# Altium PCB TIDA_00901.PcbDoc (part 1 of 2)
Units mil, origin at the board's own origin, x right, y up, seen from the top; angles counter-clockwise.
Board outline 2500 x 2500 mil, 4 copper layers (Top Layer, GND, PVDD, Bottom Layer), stack 59.2 mil thick; 113 components, 73 nets, 335 pads, 307 vias.
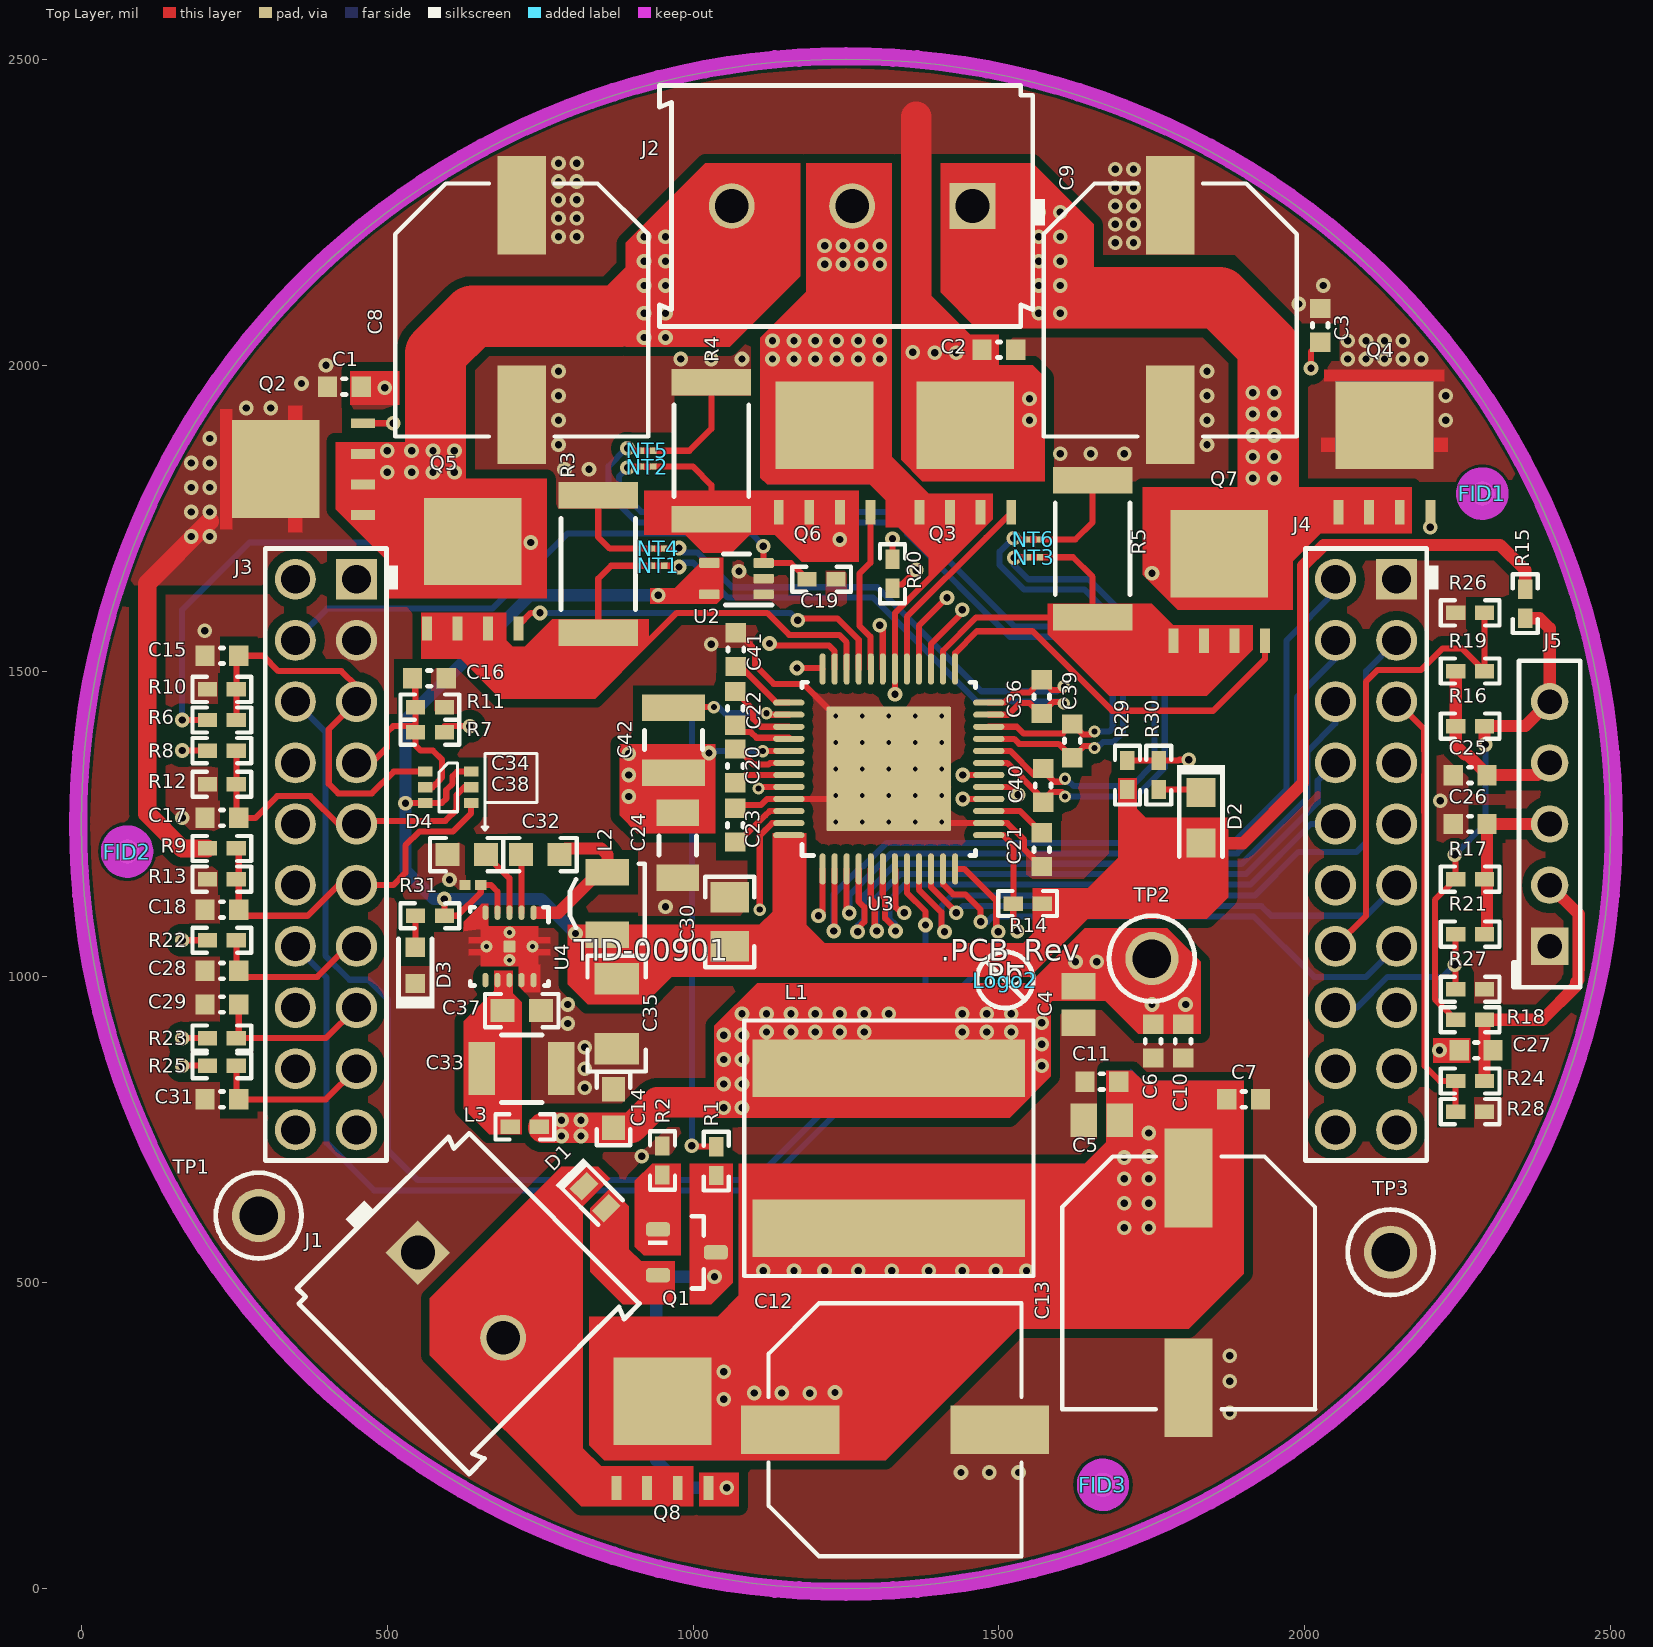
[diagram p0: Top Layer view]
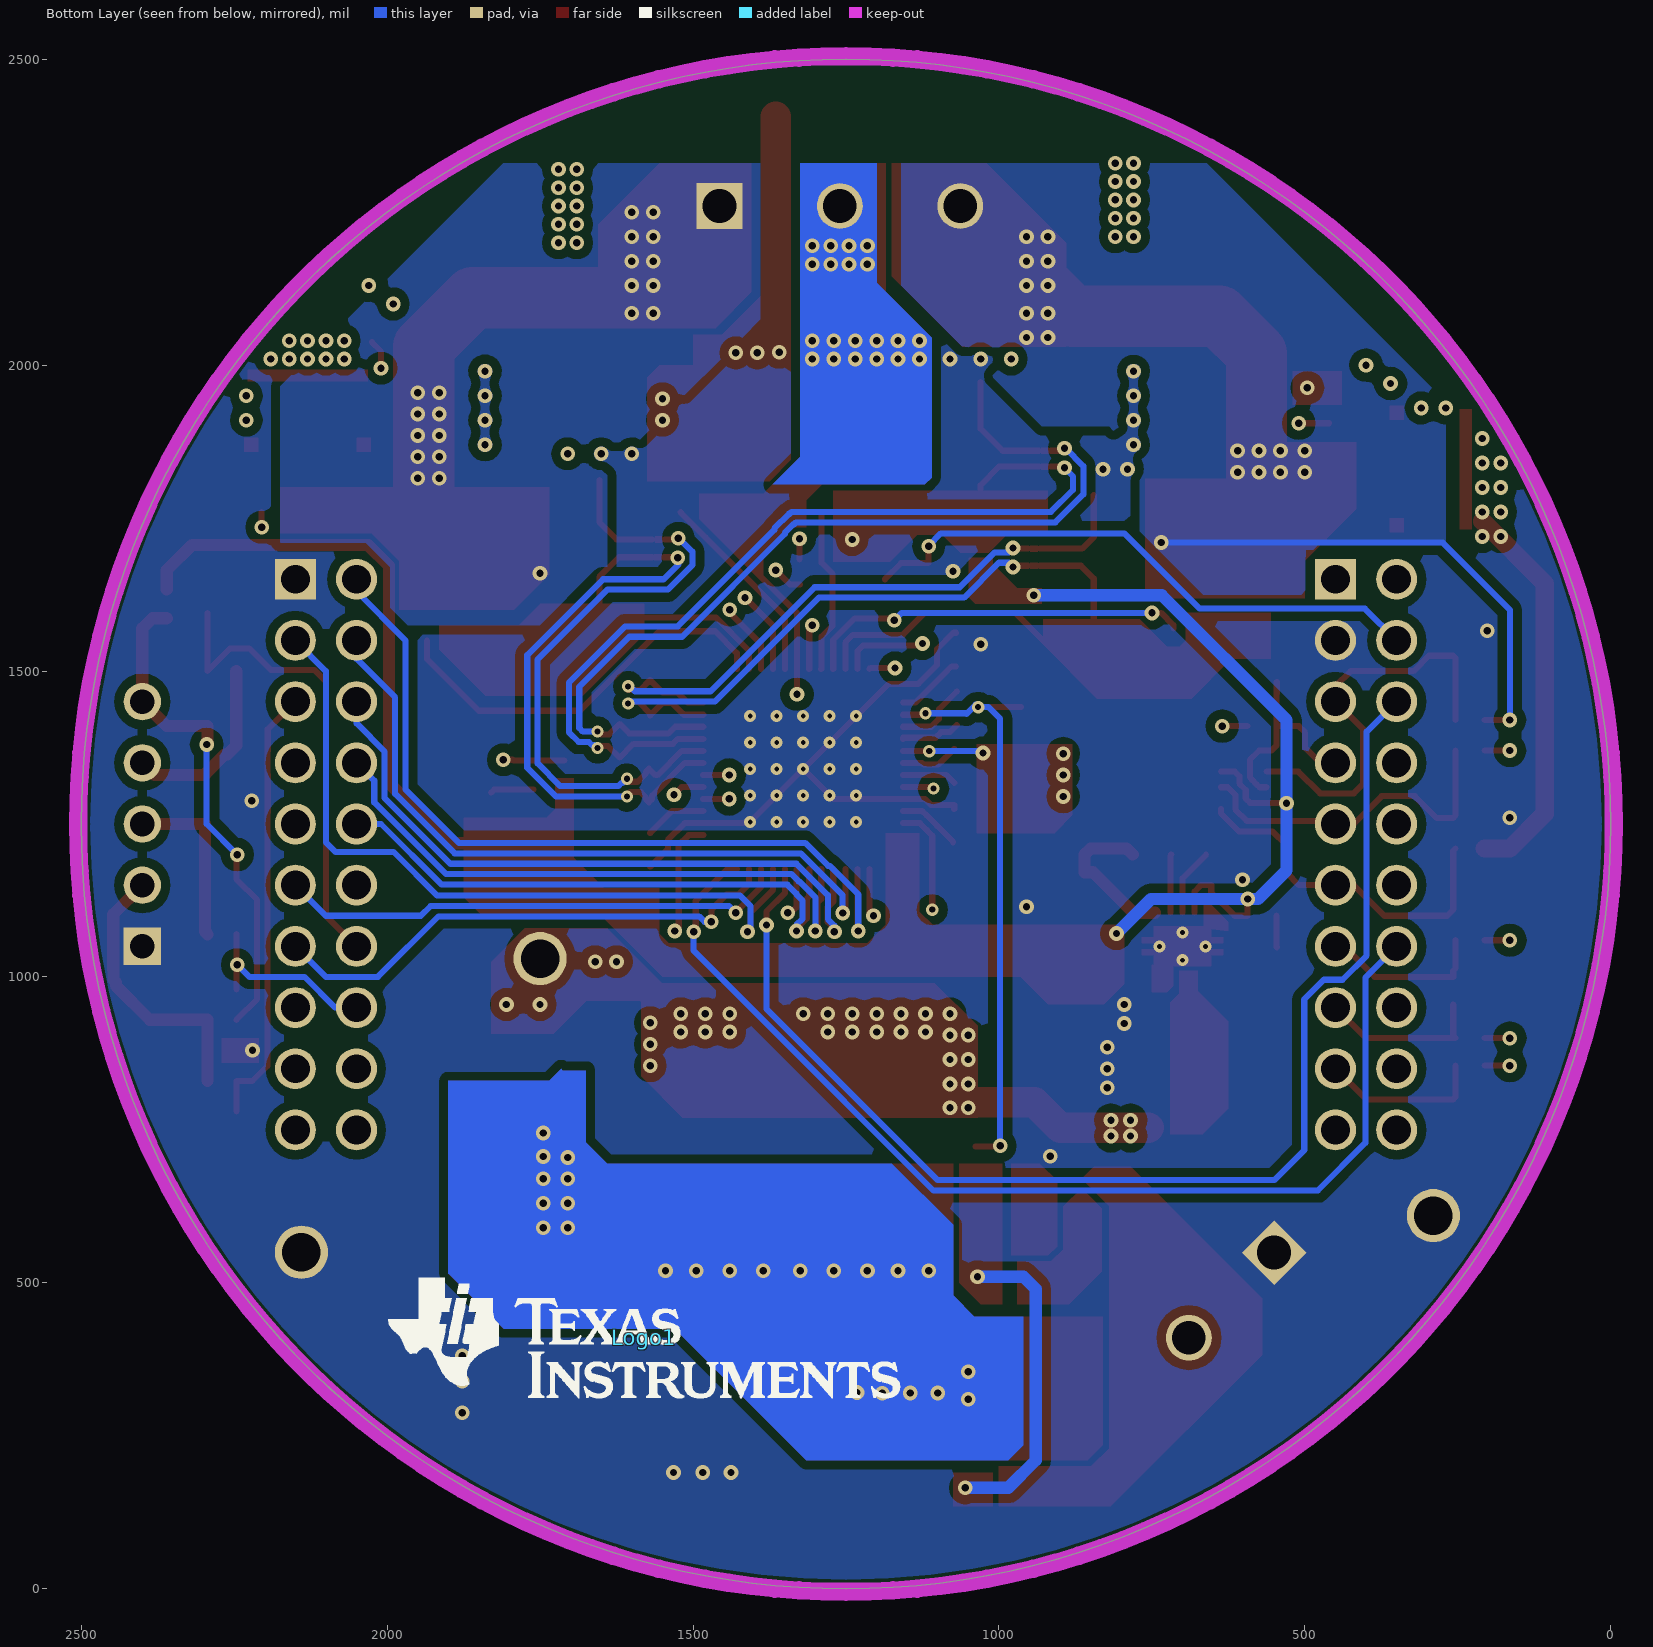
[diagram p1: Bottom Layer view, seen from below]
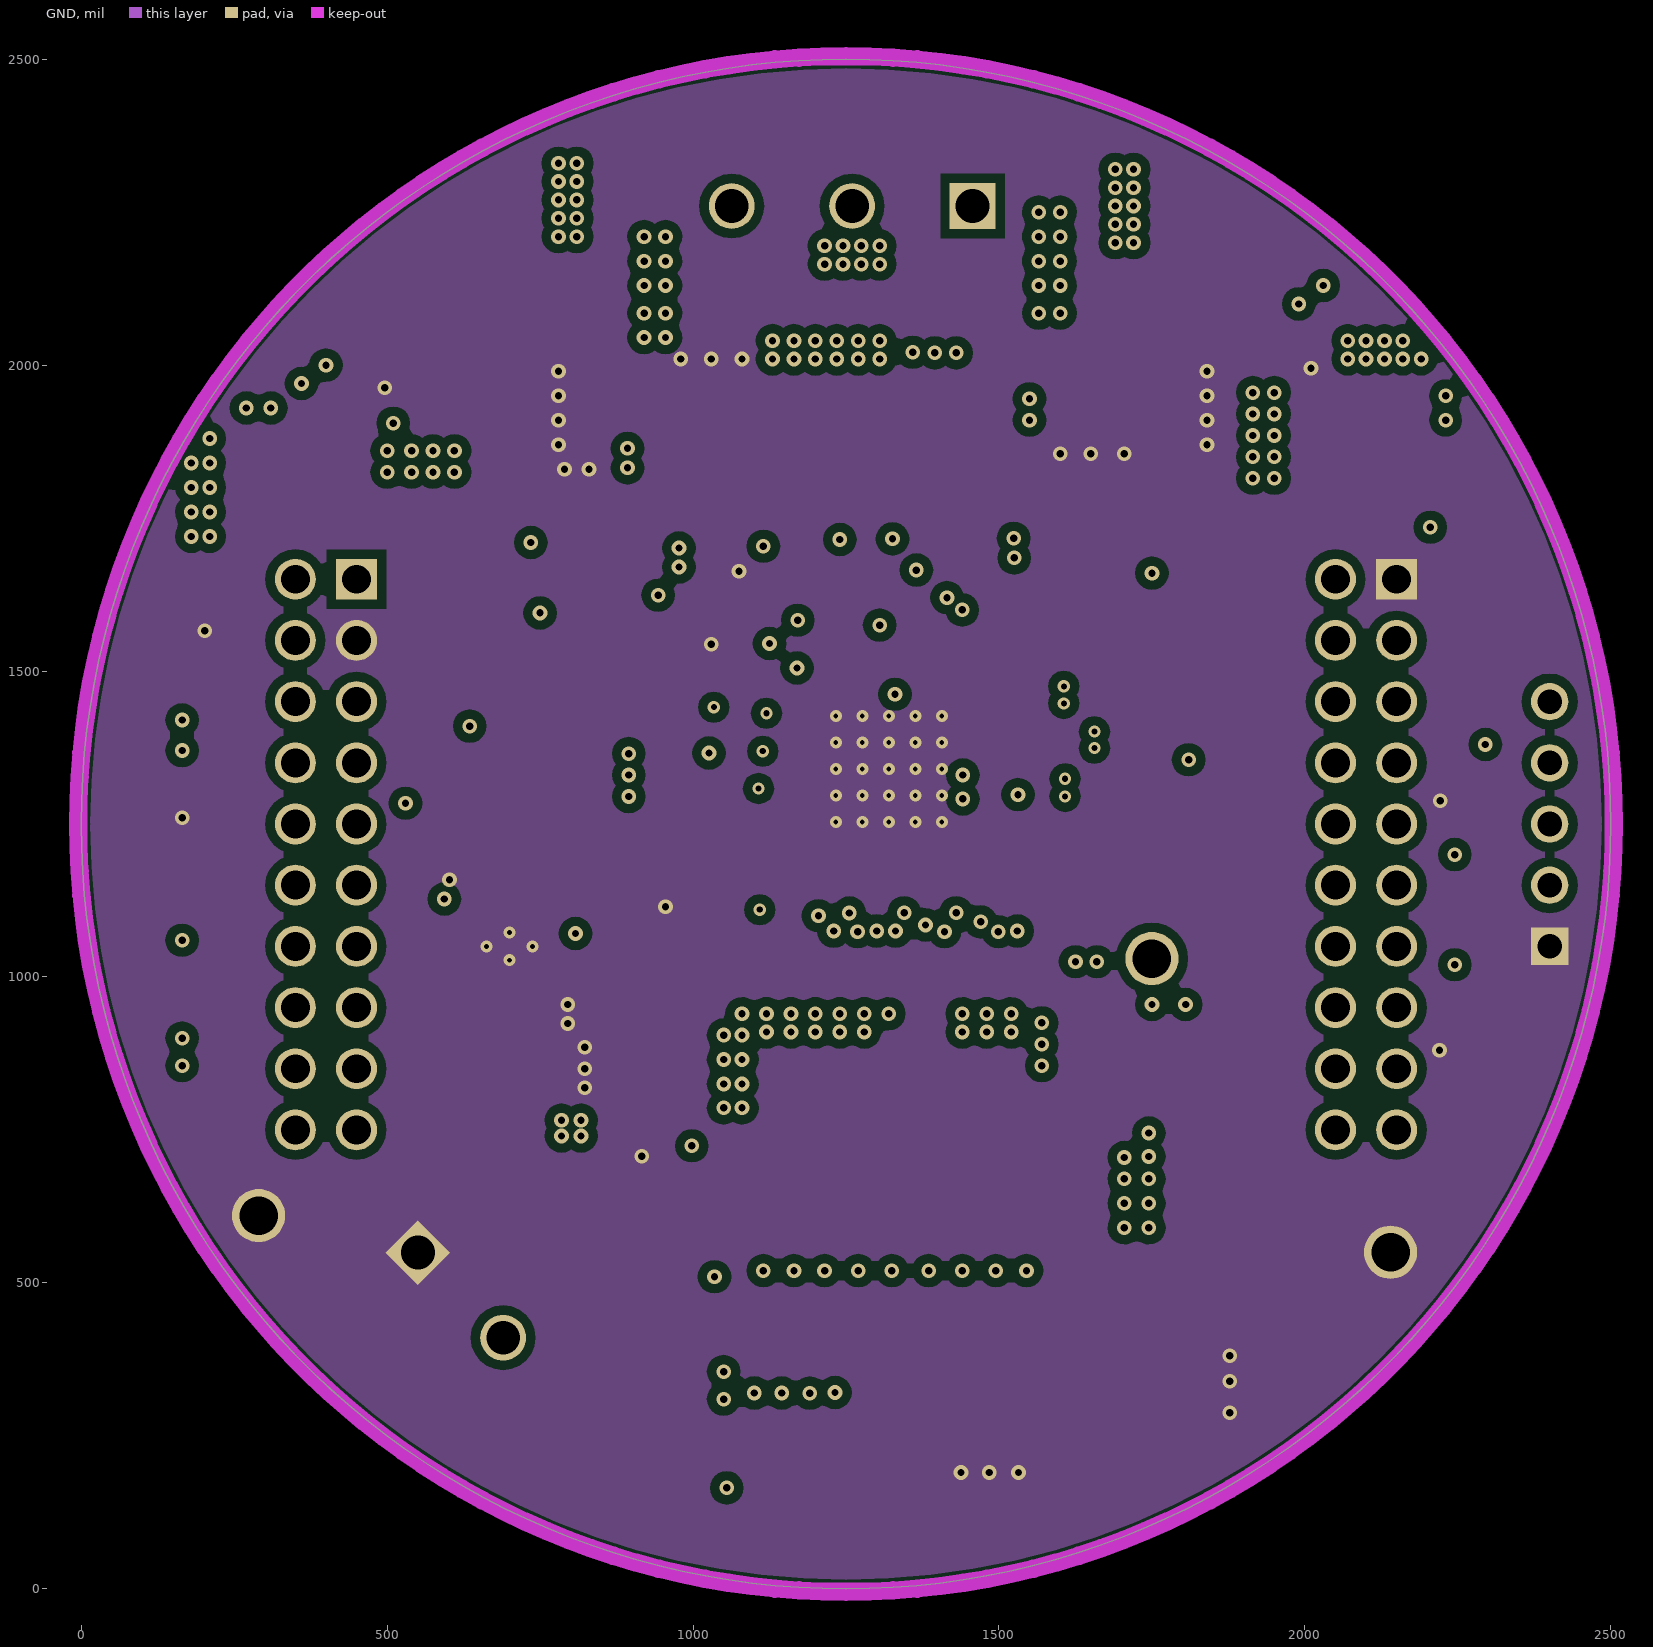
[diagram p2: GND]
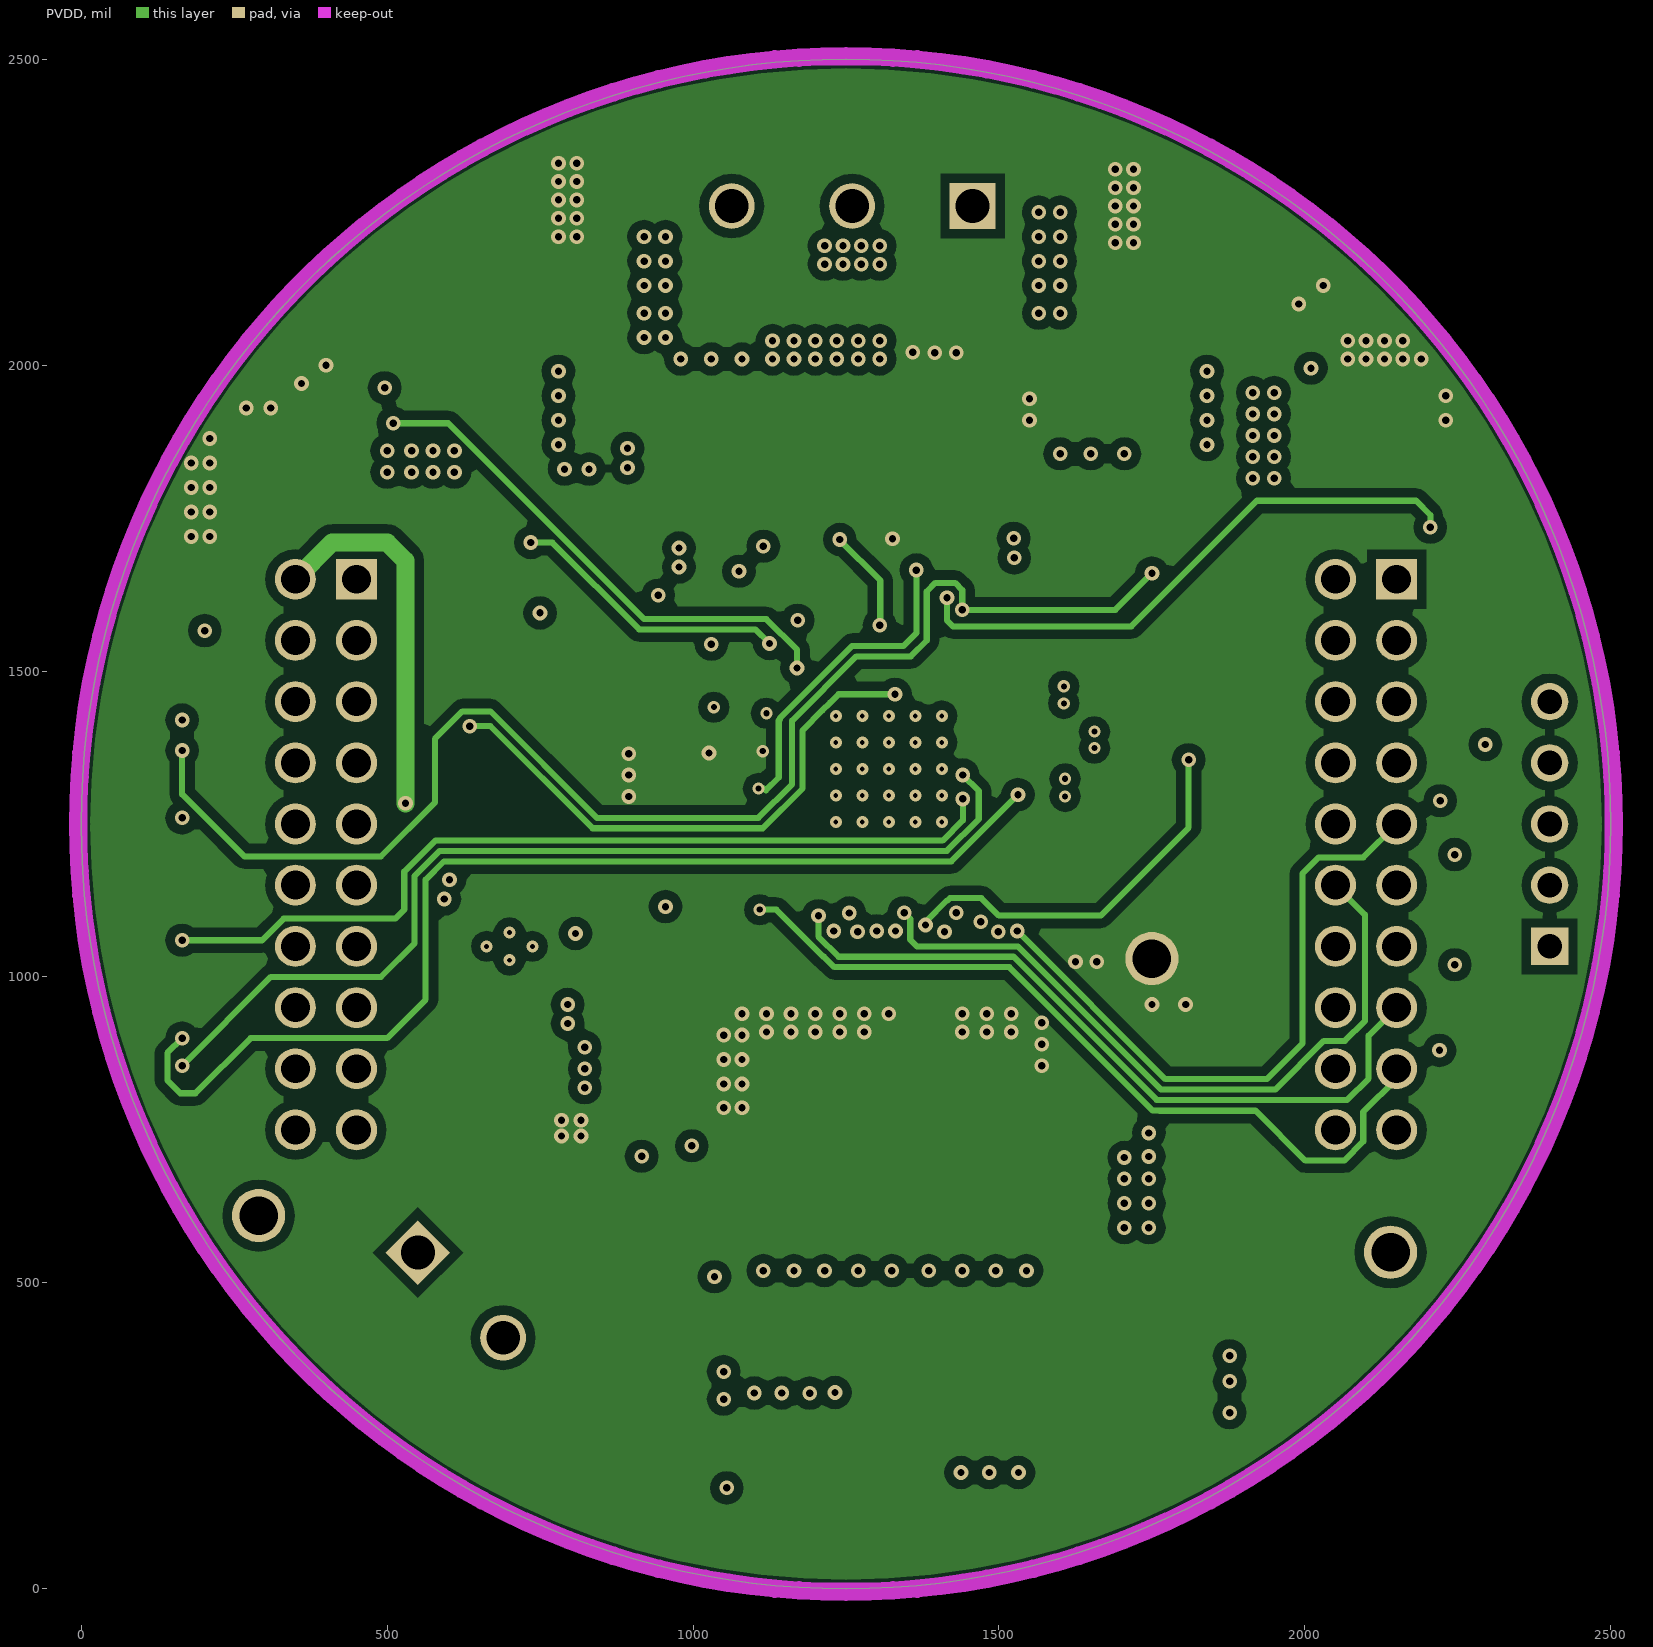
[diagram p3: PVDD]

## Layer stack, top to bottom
Top Solder: solder mask 0.4, Solder Resist, Dk 3.5
Top Layer: signal copper 2.8
Dielectric1: prepreg 10, FR-4, Dk 4.2
GND: signal copper 2.8
Dielectric 3: core 28, FR-4, Dk 4.2
PVDD: signal copper 2.8
Dielectric 2: prepreg 10, FR-4, Dk 4.2
Bottom Layer: signal copper 2.8
Bottom Solder: solder mask 0.4, Solder Resist, Dk 3.5

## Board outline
1250,0 cw(c1250,1250) 0,1250 cw(c1250,1250) 1250,2500 cw(c1250,1250) 2500,1250 cw(c1250,1250)

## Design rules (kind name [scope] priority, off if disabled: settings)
AcuteAngle [All] p1: minimum=4.50000000000000E+0001 checktracksonly=FALSE
AssemblyTestPointUsage [All] p1: valid=2
Clearance Clearance_Keepouts [((IsTrack Or IsArc) And Not InPoly) And IsFree and IsKeepOut vs ((IsTrack Or IsArc) And Not InPoly) And IsFree and IsKeepOut] p1: gap=0
Clearance Clearance_BoardEdge_MountingHoles [OnCopper and InComponentClass('Mounting Holes') vs IsKeepOut] p2: gap=20
Clearance Clearance_BoardEdge_Poly [OnCopper and InPoly vs IsKeepOut] p3: gap=5
Clearance Clearance_BoardEdge [OnCopper and Not InComponentClass('Logo') and not InComponentClass('FiducialMark') and not InRegion(1000,500,4000,800) and Not IsKeepout vs IsKeepOut] p4: gap=5
Clearance Clearance_Poly [InPolygon] p5: gap=15
Clearance [All] p6: gap=7
ComponentClearance ComponentClearance_MountingHoles_FiducialMarks [InComponentClass('Mounting Holes') vs InComponentClass('FiducialMark')] p1: gap=20 collisioncheckmode=3 verticalgap=10 showdistances=FALSE
ComponentClearance ComponentClearance_Shunt [InComponentClass('Header') vs InComponentClass('Shunt')] p2: gap=0 collisioncheckmode=3 verticalgap=0 showdistances=FALSE
ComponentClearance ComponentClearance_Logo [InComponentClass('Logo')] p3: gap=20 collisioncheckmode=3 verticalgap=10 showdistances=FALSE
ComponentClearance ComponentClearance_ScrewToNut [(HasFootprint('NY PMS 440 0025 PH')) vs (HasFootprint('Keystone_1902C'))] p4: gap=5 collisioncheckmode=3 verticalgap=10 showdistances=FALSE
ComponentClearance ComponentClearance_MountingHoles [InComponentClass('Mounting Holes')] p5: gap=20 collisioncheckmode=3 verticalgap=0 showdistances=FALSE
ComponentClearance ComponentClearance_SmallPassives [HasFootprint('0201*') or HasFootprint('0402*') or HasFootprint('0508') or HasFootprint('0603*') or HasFootprint('0612') or HasFootprint('0805*') or HasFootprint('0815*') or HasFootprint('0830*') or HasFootprint('1206*') or HasFootprint('1210*') or HasFootprint('1808*') or HasFootprint('1812*') or HasFootprint('1825*') or HasFootprint('2010*') or HasFootprint('2220*') or HasFootprint('2225*') or HasFootprint('2512*') or HasFootprint('2728*') or HasFootprint('3518*') vs HasFootprint('0201*') or HasFootprint('0402*') or HasFootprint('0508') or HasFootprint('0603*') or HasFootprint('0612') or HasFootprint('0805*') or HasFootprint('0815*') or HasFootprint('0830*') or HasFootprint('1206*') or HasFootprint('1210*') or HasFootprint('1808*') or HasFootprint('1812*') or HasFootprint('1825*') or HasFootprint('2010*') or HasFootprint('2220*') or HasFootprint('2225*') or HasFootprint('2512*') or HasFootprint('2728*') or HasFootprint('3518*')] p6: gap=10 collisioncheckmode=3 verticalgap=10 showdistances=FALSE
ComponentClearance ComponentClearance_THtoSMT [IsThruComponent vs IsSMTComponent] p7: gap=15 collisioncheckmode=3 verticalgap=20 showdistances=FALSE
ComponentClearance ComponentClearance_THtoTH [IsThruComponent vs IsThruComponent] p8: gap=15 collisioncheckmode=3 verticalgap=20 showdistances=FALSE
ComponentClearance [All] p9: gap=15 collisioncheckmode=3 verticalgap=10 showdistances=FALSE
DiffPairsRouting [All] p1: maxlimit=100 minlimit=7 mostfreqgap=7 toplayer_minwidth=10 toplayer_maxwidth=15 toplayer_prefwidth=10 midlayer1_minwidth=10 midlayer1_maxwidth=15 midlayer1_prefwidth=10 midlayer2_minwidth=10 midlayer2_maxwidth=15 midlayer2_prefwidth=10 bottomlayer_minwidth=10 bottomlayer_maxwidth=15 bottomlayer_prefwidth=10 maxuncoupledlength=1000
FabricationTestPointUsage TestPointUsage [All] p1: valid=2 allowmultiple=FALSE
FabricationTestpoint Testpoint [All] p1: side=3 testpointundercomponent=TRUE minsize=40 maxsize=100 preferedsize=60 minholesize=0 maxholesize=40 preferedholesize=32 testpointgrid=1 allowsidetop=TRUE allowsidebottom=TRUE usegrid=TRUE gridtolerance=0.01
FanoutControl Fanout_LCC [IsLCC] p1: bgadir=Out bgaviamode=Centered fanoutstyle=Auto fanoutdirection=Alternating viagrid=1 // Fanout_LCC (Default Rule)
FanoutControl Fanout_BGA [IsBGA] p2: bgadir=Out bgaviamode=Centered fanoutstyle=Auto fanoutdirection=Alternating viagrid=1 // Fanout_BGA (Default Rule)
FanoutControl Fanout_Default [All] p4: bgadir=Out bgaviamode=Centered fanoutstyle=Auto fanoutdirection=Alternating viagrid=1 // Fanout_Default (Default Rule)
FanoutControl Fanout_Small [(CompPinCount < 5)] p5: bgadir=Out bgaviamode=Centered fanoutstyle=Auto fanoutdirection=OutThenIn viagrid=1 // Fanout_Small (Default Rule)
HoleSize [All] p1: absolutevalues=TRUE maxlimit=251 minlimit=7 maxpercent=80.000 minpercent=20.000
Length All [All] p1: maxlimit=50000 minlimit=0
MinimumAnnularRing MinimumAnnularRing_ThermalPadVias [IsVia and InAnyComponent] p1: minimumring=3
MinimumAnnularRing [All] p2: minimumring=5
MinimumSolderMaskSliver MinimumSolderMaskSliver_Logo [InComponentClass('Logo') vs InComponentClass('Logo')] p1: minsoldermaskwidth=0.7
MinimumSolderMaskSliver [All] p2: minsoldermaskwidth=3.94
PlaneClearance [All] p1: clearance=10
PlaneConnect [All] p1: planeconnectstyle=Direct reliefexpansion=10 reliefentries=4 reliefconductorwidth=50 reliefairgap=10
PolygonConnect [All] p1: connectstyle=Direct reliefconductorwidth=10 reliefentries=4 polygonreliefangle="90 Angle" airgapwidth=10
RoutingVias ThermalPadVias [IsVia and InAnyComponent] p1: holewidth=7.87 width=19.68 viastyle="Through Hole" minholewidth=7.87 minwidth=19.68 maxholewidth=12.99 maxwidth=23.62
RoutingVias [All] p2: holewidth=16 width=34 viastyle="Through Hole" minholewidth=5 minwidth=15 maxholewidth=40 maxwidth=65
SilkToBoardRegionClearance [Not ((IsComment or IsDesignator) And (Hide <> 'False')) and not InRegion(1000,500,4000,800)] p1:
SilkToSilkClearance SilkToSilkClearance_Pb-FreeLogo [(HasFootprint('Pb-Free_Overlay_Medium') OR HasFootprint('Pb-Free_Overlay_Small')) vs (HasFootprint('Pb-Free_Overlay_Medium') OR HasFootprint('Pb-Free_Overlay_Small'))] p1: silktosilkclearance=0
SilkToSilkClearance [All] p2: silktosilkclearance=4
SilkToSolderMaskClearance SilkToComonentPadClearance [IsPad and InAnycomponent] p1: minsilkscreentomaskgap=5 clearancetoexposedcopper=TRUE
SilkToSolderMaskClearance "Silk to Solder Mask Opening" [All] p2: minsilkscreentomaskgap=4 clearancetoexposedcopper=FALSE
SolderMaskExpansion [All] p1: expansion=1.97
UnpouredPolygon [All] p1: allowunpoured=FALSE
Width [All] p1: maxlimit=100 minlimit=6 preferedwidth=10 checkconnectedcopper=TRUE
13 further rules are at their usual default settings.

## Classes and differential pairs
component class "TIDA 00901 Schematic 2": C1 C2 C3 C4 C5 C6 C7 C8 C9 C10 C11 C12 C13 C14 C15 C16 C17 C18 C19 C20 C21 C22 C23 C24 C25 C26 C27 C28 C29 C30 C31 C32 C33 C34 C35 C36 C37 C38 C39 C40 C41 C42 D1 D2 D3 D4 J1 J2 J3 J4 J5 L1 L2 L3 NT1 NT2 NT3 NT4 NT5 NT6 Q1 Q2 Q3 Q4 Q5 Q6 Q7 Q8 R1 R2 R3 R4 R5 R6 R7 R8 R9 R10 R11 R12 R13 R14 R15 R16 R17 R18 R19 R20 R21 R22 R23 R24 R25 R26 R27 R28 R29 R30 R31 TP1 TP2 TP3 U2 U3 U4
component class Logo: Logo1
component class TID_Hardware: FID1 FID2 FID3 Logo1 Logo2 ZZ1 ZZ2 ZZ3
component class FiducialMark: FID1 FID2 FID3
component class AssemblyNote: ZZ1 ZZ2 ZZ3
differential pair S1: +S1_P -S1_N
differential pair S2: +S2_P -S2_N
differential pair S3: +S3_P -S3_N

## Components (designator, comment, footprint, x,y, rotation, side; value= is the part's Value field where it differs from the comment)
C1 "UMK107AB7105KA-T" 0603L 430,1965 r0 top
C2 "UMK107AB7105KA-T" 0603L 1500,2025 r0 top
C3 "UMK107AB7105KA-T" 0603L 2025,2065 r270 top
C4 "GRM21BR71H105KA12L" 0805L 1630,955 r270 top
C5 "GRM21BR71H105KA12L" 0805L 1668,766 r180 top
C6 "C1608X7R1H104K" 0603L 1752,895 r270 top
C7 "C1608X7R1H104K" 0603L 1900,800 r0 top
C8 "EEE-FT1H331AP" SM_RADIAL_G 720,2090 r270 top
C9 "EEE-FT1H331AP" SM_RADIAL_G 1780,2090 r270 top
C10 "C1608X7R1H103K" 0603L 1801,895 r270 top
C11 "C1608X7R1H103K" 0603L 1668,829 r180 top
C12 "EEE-FT1H331AP" SM_RADIAL_G 1330,260 r0 top
C13 "EEE-FT1H331AP" SM_RADIAL_G 1810,500 r270 top
C14 "GRM188R71H104KA93D" 0603 870,785 r90 top
C15 "C0603C104J4RACTU" 0603L 230,1525 r180 top
C16 "C0603C104J4RACTU" 0603L 569,1488 r0 top
C17 "C0603C104J4RACTU" 0603L 230,1260 r180 top
C18 "C0603C104J4RACTU" 0603L 230,1110 r180 top
C19 "C0402C104K4RACAUTO" 0402 1210,1650 r0 top
C20 "C0603C473K1RACTU" 0603L 1069,1345 r90 top
C21 "C1608X7R1C105K" 0603L 1570,1208 r90 top
C22 "C0603C473K1RACTU" 0603L 1069,1439 r270 top
C23 "C1608X7R1C105K" 0603L 1069,1248 r270 top
C24 "GRM31CR71H475KA12L" 1206L 975,1215 r90 top
C25 "GRM188R71C102KA01D" 0603L 2270,1330 r180 top
C26 "GRM188R71C102KA01D" 0603L 2270,1250 r180 top
C27 "GRM188R71C102KA01D" 0603L 2280,880 r180 top
C28 "GRM188R71C222KA01D" 0603L 230,1010 r180 top
C29 "GRM188R71C222KA01D" 0603L 230,955 r180 top
C30 "C2012X7R1A106M125AC" 0805_HV 1060,1090 r90 top
C31 "GRM188R71C222KA01D" 0603L 230,800 r180 top
C32 "GRM188R71H104KA93D" 0603 750,1200 r0 top
C33 "C3225X7R1H106M250AC" 1210_280 720,850 r0 top
C34 "GRM188R71C105KA12D" 0603 630,1200 r180 top
C35 "GRM31CR71A226KE15L" 1206 875,940 r270 top
C36 "GRM188R71C102KA01D" 0603L 1570,1458 r90 top
C37 "GRM188R71H104KA93D" 0603 720,945 r0 top
C38 "GRM033R71A103KA01D" 0201 640,1150 r180 top
C39 "GRM188R71C102KA01D" 0603L 1620,1386 r90 top
C40 "GRM188R71C102KA01D" 0603L 1572,1313 r90 top
C41 "C1608X7R1C105K" 0603L 1070,1535 r90 top
C42 "GRM32ER72A225KA35L" 1210L 968,1387 r270 top
D1 "CD0603-S0180" Diode_0603 840,640 r315 top
D2 "LTST-C170KRKT" LED_LTST-C170 1830,1260 r90 top
D3 "LTST-C190KFKT" LED_LTST-C190 546,1019 r270 top
D4 "BAT54CDW-7-F" SOT-363 600,1310 r0 top
FID1 "Fiducial" Fiducial10-20 2290,1790 r0 top
FID2 "Fiducial" Fiducial10-20 75,1205 r0 top
FID3 "Fiducial" Fiducial10-20 1670,170 r0 top
J1 "282856-2" TE_282856-2 620,480 r315 top
J2 "282856-3" TE_282856-3 1260,2260 r180 top
J3 "CRD-081413-A-G" Major_CRD-081413-A-x 400,1200 r0 top locked
J4 "CRD-081413-A-G" Major_CRD-081413-A-x 2100,1200 r0 top locked
J5 "PPTC051LFBN-RC" Sullins_PPTC051LFBN-RC 2400,1250 r90 top
L1 "XAL1010-222MEB" XAL1010 1320,720 r90 top
L2 "SPM3012T-4R7M" SPM3012 860,1120 r270 top
L3 "BLM15AX601SN1D" 0402 725,755 r180 top
Logo1 "Texas Instruments" TI_Stacked_Overlay_Small 1580,410 r180 bottom
Logo2 "Pb-Free Symbol" Pb-Free_Overlay_Small 1510,995 r0 top
NT1 "Net-Tie" Net-Tie_10mil 943,1672 r180 top net-tie
NT2 "Net-Tie" Net-Tie_10mil 925,1834 r0 top net-tie
NT3 "Net-Tie" Net-Tie_10mil 1557,1686 r0 top net-tie
NT4 "Net-Tie" Net-Tie_10mil 943,1700 r180 top net-tie
NT5 "Net-Tie" Net-Tie_10mil 925,1860 r0 top net-tie
NT6 "Net-Tie" Net-Tie_10mil 1556,1715 r0 top net-tie
Q1 "BC846BLT1G" SOT-23 990,550 r0 top
Q2 "SQJ858AEP" PowerPAK_SO-8L 350,1830 r180 top
Q3 "SQJ858AEP" PowerPAK_SO-8L 1445,1870 r90 top
Q4 "SQJ858AEP" PowerPAK_SO-8L 2130,1870 r90 top
Q5 "SQJ858AEP" PowerPAK_SO-8L 640,1680 r90 top
Q6 "SQJ858AEP" PowerPAK_SO-8L 1215,1870 r90 top
Q7 "SQJ858AEP" PowerPAK_SO-8L 1860,1660 r90 top
Q8 "SQJ422EP-T1-GE3" PowerPAK_SO-8L 950,275 r90 top
R1 "CRCW040210K0JNED" 0402 1038,699 r270 top
R2 "CRCW040210K0JNED" 0402 950,700 r90 top
R3 "CRE2512-FZ-R007E-3" 2512L 845,1675 r270 top
R4 "CRE2512-FZ-R007E-3" 2512L 1030,1860 r270 top
R5 "CRE2512-FZ-R007E-3" 2512L 1653,1700 r270 top
R6 "CRCW040225K5FKED" 0402 230,1420 r180 top
R7 "CRCW040225K5FKED" 0402 570,1400 r0 top
R8 "CRCW040225K5FKED" 0402 230,1370 r180 top
R9 "CRCW040225K5FKED" 0402 230,1210 r180 top
R10 "CRCW04024K99FKED" 0402 230,1470 r0 top
R11 "CRCW04024K99FKED" 0402 570,1441 r180 top
R12 "CRCW04024K99FKED" 0402 230,1315 r0 top
R13 "CRCW04024K99FKED" 0402 230,1160 r0 top
R14 "CRCW040210K0JNED" 0402 1547,1120 r0 top
R15 "ERJ-2GE0R00X" 0402 2360,1610 r90 top
R16 "CRCW04021K00JNED" 0402 2270,1410 r0 top
R17 "CRCW04021K00JNED" 0402 2270,1160 r180 top
R18 "CRCW04021K00JNED" 0402 2270,930 r180 top
R19 "CRCW040210K0JNED" 0402 2270,1500 r0 top
R20 "CRCW0402100RFKED" 0402 1326,1659 r90 top
R21 "CRCW040210K0JNED" 0402 2270,1070 r180 top
R22 "CRCW040256R0JNED" 0402 230,1060 r180 top
R23 "CRCW040256R0JNED" 0402 230,900 r180 top
R24 "CRCW040210K0JNED" 0402 2270,830 r180 top
R25 "CRCW040256R0JNED" 0402 230,855 r180 top
R26 "CRCW040215K0JNED" 0402 2270,1595 r0 top
R27 "CRCW040215K0JNED" 0402 2270,980 r180 top
R28 "CRCW040215K0JNED" 0402 2270,780 r180 top
R29 "CRCW040210K0JNED" 0402 1710,1330 r270 top
R30 "CRCW0402330RJNED" 0402 1761,1330 r270 top
R31 "CRCW0402330RJNED" 0402 570,1100 r0 top
TP1 "5006" Keystone5006 290,610 r90 top
TP2 "5005" Keystone5005 1750,1030 r90 top
TP3 "5006" Keystone5006 2140,550 r90 top
U2 "LMT86QDCKRQ1" DCK0005A_N 1071,1651 r180 top
U3 "DRV8305NPHPQ1" PHP0048G_L 1320,1340 r90 top
U4 "LM53600NQDSXRQ1" DSX0010A 700,1050 r270 top
ZZ1 "These assemblies are ESD sensitive, ESD precautions shall be observed." AssemblyNote 125,3107.11 r0 top
ZZ2 "These assemblies must be clean and free from flux and all contaminants. Use of no clean flux is not acceptable." AssemblyNote 125,3018.56 r0 top
ZZ3 "These assemblies must comply with workmanship standards IPC-A-610 Class 2, unless otherwise specified." AssemblyNote 125,2930 r0 top

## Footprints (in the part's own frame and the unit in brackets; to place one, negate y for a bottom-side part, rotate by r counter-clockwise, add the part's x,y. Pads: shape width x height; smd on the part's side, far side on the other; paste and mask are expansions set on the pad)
0201 [mm] "Data from Kemet datasheet CC101_COM dated 7/28/11"
  rect 0.46x0.42 smd mask+0.048: 1(-0.33,0) 2(0.33,0)
  body extent -0.31,-0.16 0.31,0.16, height 0.26
0402 [mm] "0402 from SM-752 data"
  rect 0.8x0.6 smd: 1(-0.6,0) 2(0.6,0)
  silkscreen extent -1.22,-0.52 1.22,0.52, body extent -0.55,-0.3 0.55,0.3, height 0.6
0603 [mm] "0603 from SM-752 data"
  rect 1x0.95 smd: 1(-0.8,0) 2(0.8,0)
  silkscreen extent -1.52,-0.69 1.52,0.69, body extent -0.87,-0.47 0.87,0.47, height 1
0603L [mm] "0603 from SM-752 data"
  rect 0.8x0.85 smd: 1(-0.7,0) 2(0.7,0)
  silkscreen extent -0.07,-0.33 0.07,0.33, body extent -0.87,-0.47 0.87,0.47, height 1
0805_HV [mil] "0805 with 30mil clearance between pads"
  rect 50x63 smd: 1(-40,0) 2(40,0)
  silkscreen extent -74,-40 74,40, body extent -43,-29 43,29, height 57
0805L [mm] "0805 from SM-752 data"
  rect 1.1x1.4 smd: 1(-0.75,0) 2(0.75,0)
  body extent -1.1,-0.72 1.1,0.72, height 1.45
1206 [mm] "1206 from SM-752 data"
  rect 1.3x1.85 smd: 1(-1.45,0) 2(1.45,0)
  silkscreen extent -2.4,-1.21 2.4,1.21, body extent -1.7,-0.9 1.7,0.9, height 1.35
1206L [mm] "1206 from SM-752 data"
  rect 1.1x1.75 smd: 1(-1.35,0) 2(1.35,0)
  silkscreen extent -0.4,-0.77 0.4,0.77, body extent -1.7,-0.9 1.7,0.9, height 1.35
1210_280 [mm] "SMD, 2-Leads, Body 3.6x2.8mm, Height 2.8mm"
  rect 1.1x2.2 smd: 1(-1.65,0) 2(1.65,0)
  silkscreen extent -0.84,-1.4 0.84,1.4, body extent -1.8,-1.4 1.8,1.4, height 2.8
1210L [mm] "1210 from SM-752 data"
  rect 1.1x2.6 smd: 1(-1.35,0) 2(1.35,0)
  silkscreen extent -0.4,-1.2 0.4,1.2, body extent -1.7,-1.35 1.7,1.35, height 1.35
2512L [mm] "Chip Resistor, Body 6.3x3.2mm, IPC High Density"
  rect 1.1x3.3 smd: 1(-2.85,0) 2(2.85,0)
  silkscreen extent -1.9,-1.55 1.9,1.55, body extent -3.22,-1.67 3.22,1.67, height 0.71
AssemblyNote [mil] "Assembly Note"
DCK0005A_N [mm] "SOT353, 5-Leads, Body 2x1.3mm, Pitch 0.65mm, Lead Span 2.1mm, IPC Medium Density"
  rrect25% 0.85x0.4 smd: 1(-1.125,0.65) 2(-1.125,0) 3(-1.125,-0.65) 4(1.125,-0.65) 5(1.125,0.65)
  silkscreen extent -1.48,-1.02 0.55,1.1, body extent -1.14,-1 1.14,1, height 0.95
Diode_0603 [mm] "Based on Bourns recommended land pattern Rev 10/09"
  rect 0.7x1 smd: 1(-0.65,0) 2(0.65,0)
  silkscreen extent -1.5,-0.8 0.9,0.8, body extent -0.9,-0.5 0.9,0.5, height 0.85
DSX0010A [mm] "SON, 10-Leads, Body 3x3 mm, Pitch 0.5mm"
  rrect100% 0.6x0.25 smd mask+0.07: 1(-1.4,1) 2(-1.4,0.5) 3(-1.4,0) 4(-1.4,-0.5) 5(-1.4,-1) 6(1.4,-1) 7(1.4,-0.5) 8(1.4,0) 9(1.4,0.5) 10(1.4,1)
  rrect20% 0.5x0.5 smd paste-0.5: 11(0,0)
  Top Layer region: -0.375,-1.7 -0.375,-1.2 -0.825,-1.2 -0.825,1.2 -0.375,1.2 -0.375,1.7 -0.125,1.7 -0.125,1.2 0.125,1.2 0.125,1.7 0.375,1.7 0.375,1.2 0.825,1.2 0.825,-1.2 0.375,-1.2 0.375,-1.7 0.125,-1.7 0.125,-1.2 -0.125,-1.2 -0.125,-1.7
  silkscreen extent -1.63,-1.63 1.63,1.63, body extent -1.53,-1.53 1.53,1.53, height 0.81
Fiducial10-20 [mm]
  round 1 smd mask+0.5: 1(0,0)
  Top Layer keep-out circle w1.178: c0,0 r0.5
Keystone5005 [mil] "Keystone Compact loops"
  round 87 hole 63: 1(0,0)
  silkscreen extent -70,-70 70,70, body extent -63,-63 62,63, height 225
Keystone5006 [mil] "Keystone Compact loops"
  round 87 hole 63: 1(0,0)
  silkscreen extent -70,-70 70,70, body extent -63,-63 62,63, height 225
LED_LTST-C170 [mm] "LITE-ON"
  rect 1.2x1.2 smd: 1(-1.05,0) 2(1.05,0)
  silkscreen extent -1.6,-1 2.2,1, body extent -1.05,-0.67 1.05,0.67, height 1.1
LED_LTST-C190 [mm] "Lite-On"
  rect 0.8x0.8 smd: 1(-0.75,0) 2(0.75,0)
  silkscreen extent -1.1,-0.8 1.8,0.8, body extent -0.85,-0.45 0.85,0.45, height 0.9
Major_CRD-081413-A-x [mm] "Receptacle, 2.54 mm, 10x2, TH"
  rect 1.7x1.7 hole 1.2: 1(1.27,11.43)
  round 1.7 hole 1.2: 2(-1.27,11.43) 3(1.27,8.89) 4(-1.27,8.89) 5(1.27,6.35) 6(-1.27,6.35) 7(1.27,3.81) 8(-1.27,3.81) 9(1.27,1.27) 10(-1.27,1.27) 11(1.27,-1.27) 12(-1.27,-1.27) 13(1.27,-3.81) 14(-1.27,-3.81) 15(1.27,-6.35) 16(-1.27,-6.35) 17(1.27,-8.89) 18(-1.27,-8.89) 19(1.27,-11.43) 20(-1.27,-11.43)
  silkscreen extent -2.52,-12.71 3,12.71, body extent -2.52,-12.71 2.52,12.71, height 8.64
Net-Tie_10mil [mil] "10mil net tie, no solder mask opening, no solder paste"
  rect 10x10 smd paste-5 mask-5: 1(-10,0) 2(10,0)
  Top Layer region: -6,5 6,5 6,-5 -6,-5
Pb-Free_Overlay_Small [mil]
  silkscreen extent -46,-46 46,46
PHP0048G_L [mm] "QFP, 48-Leads, Body 7x7mm, Pitch 0.5mm, Thermal Pad 5.17X5.17mm, IPC High Density"
  oval 1.3x0.25 smd: 1(-4.15,2.75) 2(-4.15,2.25) 3(-4.15,1.75) 4(-4.15,1.25) 5(-4.15,0.75) 6(-4.15,0.25) 7(-4.15,-0.25) 8(-4.15,-0.75) 9(-4.15,-1.25) 10(-4.15,-1.75) 11(-4.15,-2.25) 12(-4.15,-2.75) 25(4.15,-2.75) 26(4.15,-2.25) 27(4.15,-1.75) 28(4.15,-1.25) 29(4.15,-0.75) 30(4.15,-0.25) 31(4.15,0.25) 32(4.15,0.75) 33(4.15,1.25) 34(4.15,1.75) 35(4.15,2.25) 36(4.15,2.75)
  oval 0.25x1.3 smd: 13(-2.75,-4.15) 14(-2.25,-4.15) 15(-1.75,-4.15) 16(-1.25,-4.15) 17(-0.75,-4.15) 18(-0.25,-4.15) 19(0.25,-4.15) 20(0.75,-4.15) 21(1.25,-4.15) 22(1.75,-4.15) 23(2.25,-4.15) 24(2.75,-4.15) 37(2.75,4.15) 38(2.25,4.15) 39(1.75,4.15) 40(1.25,4.15) 41(0.75,4.15) 42(0.25,4.15) 43(-0.25,4.15) 44(-0.75,4.15) 45(-1.25,4.15) 46(-1.75,4.15) 47(-2.25,4.15) 48(-2.75,4.15)
  rrect2% 5.17x5.17 smd: 49(0,0)
  silkscreen extent -3.6,-3.6 3.6,3.6, body extent -4.51,-4.51 4.51,4.51, height 1.2
PowerPAK_SO-8L [mm] "based on Vishay recommended land pattern Document 63818 Feb 7, 2012"
  rect 1x0.41 smd: 1(-2.805,1.905) 2(-2.805,0.635) 3(-2.805,-0.635) 4(-2.805,-1.905)
  rect 3.63x4.061 smd: 5(0.805,0)
  Top Layer region: 2.615,-2.5 3.125,-2.5 3.125,2.5 2.615,2.5
  Top Layer region: -0.298,2.03 0.297,2.03 0.297,2.64 -0.298,2.64
  Top Layer region: -0.298,-2.64 0.298,-2.64 0.298,-2.03 -0.298,-2.03
  body extent -3.07,-2.57 3.08,2.57, height 1.21
SM_RADIAL_G [mm] "10 x 10.2mm:  Panasonic G"
  rect 4.1x2 smd: 1(-4.35,0) 2(4.35,0)
  silkscreen extent -5.25,-5.25 5.25,5.25, body extent -5.26,-5.26 5.26,5.26, height 10.5
SOT-23 [mm] "SOT23, 3-Leads, Body 2.9x1.3mm, Pitch 0.95mm, Lead Span 2.5mm, IPC Medium Density"
  rrect50% 1x0.6 smd: 1(-1.2,0.95) 2(-1.2,-0.95) 3(1.2,0)
  silkscreen extent -1.63,-1.5 0.7,1.5, body extent -1.16,-1.45 1.21,1.45, height 1
SOT-363 [mm]
  rect 0.6x0.42 smd mask+0.051: 1(-0.95,0.65) 2(-0.95,0) 3(-0.95,-0.65) 4(0.95,-0.65) 5(0.95,0) 6(0.95,0.65)
  silkscreen extent -0.38,-1.02 0.38,1.02, body extent -1.1,-1.1 1.1,1.1, height 1.12
SPM3012 [mm] "SMD, 2-Leads, Body 3.2x3mm"
  rect 1.1x1.8 smd: 1(-1.3,0) 2(1.3,0)
  silkscreen extent -1.65,-1.55 1.65,1.55, body extent -1.65,-1.55 1.65,1.55, height 1.2
Sullins_PPTC051LFBN-RC [mm] "Receptacle, 5x1, 2.54mm, TH"
  rect 1.55x1.55 hole 1.02: 1(-5.08,0)
  round 1.55 hole 1.02: 2(-2.54,0) 3(0,0) 4(2.54,0) 5(5.08,0)
  silkscreen extent -6.78,-1.27 6.78,1.5, body extent -6.78,-1.27 6.78,1.27, height 8.53
TE_282856-2 [mm] "TH, 2-Leads, Body 10x10mm, Pitch 5mm"
  rect 1.9x1.9 hole 1.4: 1(-2.5,0)
  round 1.9 hole 1.4: 2(2.5,0)
  silkscreen extent -5.61,-5 5.5,5, body extent -5,-5 5.5,5, height 19
TE_282856-3 [mm] "Receptacle, 3x1, 5mm, R/A, TH"
  rect 1.9x1.9 hole 1.4: 1(-5,0)
  round 1.9 hole 1.4: 2(0,0) 3(5,0)
  silkscreen extent -8,-5 8,5, body extent -7.5,-5 8,5, height 19
TI_Stacked_Overlay_Small [mil]
  silkscreen extent -418,-98 418,98
XAL1010 [mm] "COILCRAFT"
  rect 2.38x11.31 smd: 1(-3.325,0) 2(3.325,0)
  silkscreen extent -5.3,-6 5.3,6, body extent -5.25,-5.9 5.25,5.9, height 10

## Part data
C1 C2 C3: "CAP, CERM, 1 µF, 50 V, +/- 10%, X7R, 0603"
C4 C5: "CAP, CERM, 1uF, 50V, +/-10%, X7R, 0805"
C6 C7: "CAP, CERM, 0.1uF, 50V, +/-10%, X7R, 0603"
C8 C9 C12 C13: library part EEE-FC1H221P, "CAP, AL, 330 µF, 50 V, +/- 20%, 0.3 ohm, SMD"
C10 C11: "CAP, CERM, 0.01uF, 50V, +/-10%, X7R, 0603"
C14 C32 C37: "CAP, CERM, 0.1 µF, 50 V, +/- 10%, X7R, 0603"
C15 C16 C17 C18: "CAP, CERM, 0.1 µF, 16 V, +/- 5%, X7R, 0603"
C19: "CAP, CERM, 0.1 µF, 16 V, +/- 10%, X7R, AEC-Q200 Grade 1, 0402"
C20 C22: library part GRM188R72A104KA35D, "CAP, CERM, 0.047uF, 100V, +/-10%, X7R, 0603"
C21 C23 C34 C41: "CAP, CERM, 1 µF, 16 V, +/- 10%, X7R, 0603"
C24: "CAP, CERM, 4.7 µF, 50 V, +/- 10%, X7R, 1206"
C25 C26 C27 C36 C39 C40: "CAP, CERM, 1000pF, 16V, +/-10%, X7R, 0603"
C28 C29 C31: "CAP, CERM, 2200pF, 16V, +/-10%, X7R, 0603"
C30: "CAP, CERM, 10 µF, 10 V, +/- 20%, X7R, 0805"
C33: "CAP, CERM, 10 µF, 50 V, +/- 20%, X7R, 1210"
C35: "CAP, CERM, 22 µF, 10 V, +/- 10%, X7R, 1206"
C38: "CAP, CERM, 0.01 µF, 10 V, +/- 10%, X7R, 0201"
C42: "CAP, CERM, 2.2 µF, 100 V, +/- 10%, X7R, 1210"
D1: "Diode, Switching, 90V, 0.1A, 0603 Diode"
D2: "LED, Red, SMD"
D3: "LED, Orange, SMD"
D4: "Diode, Schottky, 30 V, 0.2 A, SOT-363"
FID1 FID2 FID3: "Fiducial mark.  There is nothing to buy or mount."
J1: "Therminal Block, 5 mm, 2-pole, Tin, TH"
J2: "Receptacle, 3x1, 5mm, R/A, TH"
J3 J4: "Receptacle, 2.54 mm, 10x2, Gold, TH"
J5: "Receptacle, 2.54 mm, 5x1, Tin, TH"
L1: "Inductor, Shielded, Composite, 2.2 µH, 32 A, 0.00255 ohm, SMD"
L2: "Inductor, Shielded, Ferrite, 4.7 µH, 1.5 A, 0.27 ohm, SMD"
L3: "Ferrite Bead, 600 ohm @ 100 MHz, 0.5 A, 0402"
Logo1: library part TI_Logo, "Texas Instrument Corporate Signature"
Logo2: library part Pb-Free
NT1 NT2 NT3 NT4 NT5 NT6: "Single point connection between nets."
Q1: library part "BC846BLT1G, ON Semiconductor", "Transistor, NPN, 65V, 0.1A, SOT-23"
Q2 Q3 Q4 Q5 Q6 Q7: library part SQJ858AEP-T1-GE3, "MOSFET, N-CH, 40 V, 58 A, PowerPAK_SO-8L"
Q8: "MOSFET, N-CH, 40 V, 75 A, PowerPAK_SO-8L"
R1 R2 R14 R19 R21 R24 R29: "RES, 10 k, 5%, 0.063 W, 0402"
R3 R4 R5: library part PMR100HZPFU7L00, "RES SMD 0.007 OHM 1% 3W 2512"
R6 R7 R8 R9: "RES, 25.5 k, 1%, 0.063 W, 0402"
R10 R11 R12 R13: "RES, 4.99 k, 1%, 0.063 W, 0402"
R15: "RES, 0, 5%, 0.063 W, 0402"
R16 R17 R18: "RES, 1.0 k, 5%, 0.063 W, 0402"
R20: "RES, 100, 1%, 0.063 W, 0402"
R22 R23 R25: "RES, 56, 5%, 0.063 W, 0402"
R26 R27 R28: "RES, 15 k, 5%, 0.063 W, 0402"
R30 R31: "RES, 330, 5%, 0.063 W, 0402"
TP1 TP3: "Test Point, Compact, Black, TH"
TP2: "Test Point, Compact, Red, TH"
U2: "SC70 Analog Temperature Sensor with Class-AB Output, DCK0005A"
U3: library part DRV83053EPHPRQ1, "Three Phase Automotive Gate Driver with Three Integrated Current Shunt Amplifiers and Voltage Regulator, PHP0048G"
U4: "Synchronous Buck Regulator for 650mA Space Constraint Applications, DSX0010A"
ZZ1 ZZ2 ZZ3: library part AssemblyNote

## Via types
v1: diameter 24, hole 12, Top Layer to Bottom Layer, tented both sides, 267 vias
v2: diameter 19.68, hole 7.87, Top Layer to Bottom Layer, 29 vias
v3: diameter 20, hole 10, Top Layer to Bottom Layer, tented both sides, 11 vias

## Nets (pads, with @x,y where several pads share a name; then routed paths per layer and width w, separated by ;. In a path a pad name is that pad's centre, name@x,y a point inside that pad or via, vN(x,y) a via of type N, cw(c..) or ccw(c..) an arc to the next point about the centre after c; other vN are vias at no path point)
3.3V: C30.1 C35.1 C38.1 D2.1 D4.3 D4.6 J3.2 L2.2 R14.2 R15.2 R29.2 R31.2 U2.4 U2.5 U3.48 U4.4 | length 3093.4
  Top Layer w10: v1(530,1284) 530.41,1284.41 D4.3@562.6,1284.41 589.41,1284.41 596.59,1291.59 596.59,1305.59 607,1316 607,1328 614.59,1335.59 D4.6@637.4,1335.59 ; v1(593.62,1127.38) R31.2@593.62,1100 615,1100 652.99,1137.99 C38.1@652.99,1150 670,1150 680.32,1139.68 U4.4@680.32,1105.12 ; v1@945,1625 965.94,1625 1017.53,1676.59 U2.4@1026.71,1676.59
  Top Layer w20: D2.1@1830,1218.66 1898.66,1218.66 1997,1317 1997,1672 2031,1706 2319,1706 2360,1665 R15.2@2360,1633.62
  PVDD w30: J3.2@350,1650 410,1710 500,1710 530,1680 v1(530,1284)
  Bottom Layer w20: v1(808,1071) 751.62,1127.38 v1(593.62,1127.38) 576.62,1127.38 530,1174 v1(530,1284) 530,1420 734,1624 v1(943,1624)
AVDD: C21.2 U3.15 | length 101.3
  Top Layer w10: U3.15@1483.39,1271.1 1534.46,1271.1 C21.2@1570,1235.56
DVDD: C23.2 U3.46 | length 103.4
  Top Layer w10: C23.2@1075,1220 1075,1221 1101,1247 1117.99,1264 1125.1,1271.1 U3.46@1156.61,1271.1
EN_GATE: J4.15 U3.1 | length 1276.1
  Top Layer w10: v1(1205,1100) 1211.06,1100 1211.73,1100.67 U3.1@1211.73,1176.61
  PVDD w10: v1(1205,1100) 1205,1066 1238,1033 1523.92,1033 1757.92,799 2069,799 2104,834 2104,904 J4.15@2150,950
GH_A: Q2.4 U3.36 | length 935.2
  Top Layer w10: Q2.4@460.43,1905 v1(510,1905) ; v1(1170,1505) 1210.12,1505 U3.36@1211.73,1503.39
  PVDD w10: v1(510,1905) 600,1905 920,1585 1120,1585 1170,1535 v1(1170,1505)
GH_B: Q3.4 U3.29 | length 326.8
  Top Layer w10: U3.29@1349.53,1503.39 1349.53,1588.47 1479.06,1718 1479.06,1718.06 1520,1759 Q3.4@1520,1759.57
GH_C: Q4.4 U3.28 | length 1111.7
  Top Layer w10: U3.28@1369.21,1503.39 1369.21,1574.21 v1(1415,1620) ; v1(2205,1735) Q4.4@2205,1759.57
  PVDD w10: v1@1419,1624 v1(1415,1620) 1415,1582.75 1424.72,1573.03 1716.33,1573.03 1921.56,1778.26 2181.74,1778.26 2205,1755 v1(2205,1735)
GL_A: Q5.4 U3.33 | length 627.7
  Top Layer w10: Q5.4@715,1569.57 715,1575 735,1595 v1(750,1595) ; v1@1180,1586 1236.02,1586 1270.79,1551.23 U3.33@1270.79,1503.39
  Bottom Layer w10: v1(750,1595) 1159,1595 v1(1171,1583)
GL_B: Q6.4 U3.32 | length 271.3
  Top Layer w10: Q6.4@1290,1759.57 1290,1677 1272,1659 1272,1574.06 1290,1556.06 1290,1503.86 U3.32@1290.47,1503.39
GL_C: Q7.4 U3.25 | length 666
  Top Layer w10: U3.25@1428.27,1503.39 1428.27,1529.23 1464.04,1565 1555,1565 1685,1435 1850,1435 1935,1520 Q7.4@1935,1549.57
GND: C1.2 C2.2 C3.2 C4.2 C5.2 C6.2 C7.2 C8.2 C9.2 C10.2 C11.2 C12.2 C13.2 C14.2 C15.2 C16.2 C17.2 C18.2 C19.2 C21.1 C23.1 C24.1 C25.2 C26.2 C27.2 C28.2 C29.2 C30.2 C31.2 C33.2 C34.2 C35.2 C37.2 C38.2 C41.2 D3.2 J1.1 J3.3 J4.1 J5.1 NT4.2 NT5.2 NT6.2 R2.2 R3.1 R4.1 R5.1 R10.1 R11.1 R12.1 R13.1 R26.1 R27.1 R28.1 TP1.1 TP3.1 U2.1 U2.2 U3.14 U3.45 U3.49 U4.5 U4.9 U4.10 U4.11 | length 1518.5
  Top Layer w10: R3.1@845,1787.2 845,1719 864,1700 NT4.2@933,1700 ; NT5.2@935,1860 994,1860 1030,1896 R4.1@1030,1972.2 ; C41.2@1070,1562.56 1074.44,1562.56 1101,1536 1101,1510 1132,1479 1180,1479 1319,1340 v2(1320,1340) ; C23.1@1073,1274.56 1073,1281 1110.96,1281 1120.75,1290.79 U3.45@1156.61,1290.79 U3.49@1270.79,1290.79 ; v2(1276.69,1296.69) v2(1320,1340) ; NT6.2@1566,1715 1625,1715 1653,1743 R5.1@1653,1812.2 ; C21.1@1570,1180.44 1569.56,1180.44 1541,1209 1541,1224 1513.58,1251.42 U3.14@1483.39,1251.42 1408.58,1251.42 v2(1320,1340) ; v1(2010,1995) 2010,2022.44 C3.2@2025,2037.44
  other v1: 1438,190 1484,190 1532,190 1877,288 1877,339 1877,381 916,707 823,819 823,850 2220,880 823,885 795,924 795,955 955,1115 602,1159 165,1260 2221,1288 1030,1544 202,1566 1075,1663 790,1830 830,1830 1600,1855 1650,1855 1705,1855 780,1870 1840,1870 780,1910 1840,1910 780,1950 1840,1950 496,1963 780,1990 1840,1990 980,2010 1030,2010 1080,2010
  other v2: 700,1027.36 662.6,1050 737.4,1050 700,1072.64 1233.39,1253.39 1276.69,1253.39 1320,1253.39 1363.31,1253.39 1406.61,1253.39 1233.39,1296.69 1320,1296.69 1363.31,1296.69 1406.61,1296.69 1233.39,1340 1276.69,1340 1363.31,1340 1406.61,1340 1233.39,1383.31 1276.69,1383.31 1320,1383.31 1363.31,1383.31 1406.61,1383.31 1233.39,1426.61 1276.69,1426.61 1320,1426.61 1363.31,1426.61 1406.61,1426.61
HALL_A: C25.1 J5.4 R16.1 R19.1 | length 304.2
  Top Layer w20: R19.1@2246.38,1500 R16.1@2246.38,1410 2246.38,1378.62 2261.27,1363.73 2265.23,1363.73 2297.56,1331.4 C25.1@2297.56,1330 2380,1330 J5.4@2400,1350
HALL_B: C26.1 J5.3 R17.1 R21.1 | length 284.1
  Top Layer w20: R21.1@2293.62,1070 2297.56,1073.94 C26.1@2297.56,1250 J5.3@2400,1250
HALL_C: C27.1 J5.2 R18.1 R24.1 | length 458.7
  Top Layer w20: R24.1@2293.62,830 R18.1@2293.62,930 2388,930 2443.19,985.19 2443.19,991.32 2447.36,995.49 2447.36,1012.28 2447.51,1012.44 2447.51,1102.49 J5.2@2400,1150
ISNS_A: C28.1 J3.13 R22.1 | length 274.8
  Top Layer w10: R22.1@253.62,1060 253.62,1013.94 C28.1@257.56,1010 257.56,1000 385.93,1000 435.93,1050 J3.13@450,1050
ISNS_B: C29.1 J3.15 R23.1 | length 273.7
  Top Layer w10: C29.1@257.56,955 257.56,903.94 R23.1@253.62,900 400,900 J3.15@450,950
ISNS_C: C31.1 J3.17 R25.1 | length 269.8
  Top Layer w10: R25.1@253.62,855 253.62,803.94 C31.1@257.56,800 400,800 J3.17@450,850
MOT_A: J2.3 Q2.1 Q2.2 Q2.3 Q5.5 R6.2 U3.35 | length 2352.6
  Top Layer w10: v1(165,1420) R6.2@206.38,1420 ; v1(1125,1545) 1128,1542 1222,1542 1231.42,1532.58 U3.35@1231.42,1503.39
  Top Layer w100: Q5.5@640,1711.69 579,1772.69 579,2019 640,2080 880,2080 1060,2260 J2.3@1063.15,2260
  PVDD w10: v1(735,1710) 770,1710 912,1568 1102,1568 v1(1125,1545)
  Bottom Layer w10: v1(165,1420) 165,1600 275,1710 v1(735,1710)
  other v1: 500,1825 540,1825 575,1825 610,1825 500,1860 540,1860 575,1860 610,1860 920,2045 955,2045 920,2085 955,2085 920,2130 955,2130 920,2170 955,2170 920,2210 955,2210
MOT_B: J2.2 Q3.1 Q3.2 Q3.3 Q6.5 R7.2 U3.30 | length 1307.7
  Top Layer w10: R7.2@593.62,1410 v1(635,1410) ; v1(1330,1462) 1329.84,1462.16 U3.30@1329.84,1503.39 1329.84,1594.69 1470,1734.85 Q3.3@1470,1759.57
  PVDD w10: v1(635,1410) 668.96,1410 835.96,1243 1114,1243 1179,1308 1179,1403 1211.54,1435.54 1211.54,1435.66 1224.34,1448.46 1224.46,1448.46 1238,1462 v1(1330,1462)
  other v1: 1130,2010 1165,2010 1200,2010 1235,2010 1270,2010 1305,2010 1130,2040 1165,2040 1200,2040 1235,2040 1270,2040 1305,2040 1215,2165 1245,2165 1275,2165 1305,2165 1215,2195 1245,2195 1275,2195 1305,2195
MOT_C: J2.1 Q4.1 Q4.2 Q4.3 Q7.5 R8.2 U3.27 | length 3362.5
  Top Layer w10: v1(165,1370) R8.2@206.38,1370 ; U3.27@1388.9,1503.39 1388.9,1543.9 v1@1440,1595
  Top Layer w100: J2.1@1456.85,2260 1575.93,2140.93 1606.85,2110 1860,2110 1940,2030 1940,1920 1940,1771.69 Q7.5@1860,1691.69
  PVDD w10: v1(165,1370) 165,1298.62 266.62,1197 490,1197 578,1285 578,1389 623,1434 669,1434 843,1260 1106.96,1260 1162,1315.04 1162,1419 1267,1524 1356.09,1524 1382,1549.91 1382,1630 1396,1644 1428.2,1644 1440,1632.2 v1(1440,1600) 1690,1600 v1(1750,1660)
  other v1: 1915,1815 1950,1815 1915,1850 1950,1850 1915,1885 1950,1885 1915,1920 1950,1920 1915,1955 1950,1955 1565,2085 1600,2085 1565,2130 1600,2130 1565,2170 1600,2170 1565,2210 1600,2210 1565,2250 1600,2250
NetC5_1: C5.1 C7.1 C11.1 C12.1 C13.1 L1.1 Q8.5
  other v1: 1050,310 1100,320 1145,320 1190.69,319.85 1232.13,320.94 1050,355 1115,520 1165,520 1215,520 1270,520 1325,520 1385,520 1440,520 1495,520 1545,520 1705,590 1745,590 1705,630 1745,630 1705,670 1745,670 1705,705 1745,706.69 1745,745
NetC20_1: C20.1 U3.43 | length 88.9
  Top Layer w10: C20.1@1073,1317.44 1085.56,1330 1148.04,1330 1148.2,1330.16 U3.43@1156.61,1330.16
NetC20_2: C20.2 U3.42 | length 95.4
  Top Layer w10: C20.2@1073,1372.56 1073.44,1372.56 1099,1347 1123.11,1347 1125.96,1349.84 U3.42@1156.61,1349.84
NetC22_1: C22.1 U3.39 | length 120.7
  Top Layer w10: C22.1@1069,1466.56 1098,1437.56 1098,1421.89 1110.99,1408.9 U3.39@1156.61,1408.9
NetC22_2: C22.2 U3.40 | length 97.9
  Top Layer w10: C22.2@1069,1411.44 1080.13,1400.31 1094.7,1400.31 1104.01,1391 1156.61,1391 U3.40@1156.61,1389.21
NetC32_1: C32.1 U4.2 | length 95.4
  Top Layer w10: C32.1@718.5,1200 719.69,1198.82 U4.2@719.69,1105.12
NetC32_2: C32.2 L2.1 U4.1 | length 258
  Top Layer w20: 745,1105 780.05,1105.05 846.18,1171.18 L2.1@860,1171.18 860,1200 850,1210 791.5,1210 C32.2@781.5,1200
NetC33_1: C33.1 C37.1 L3.2 U4.7 U4.8 | length 41.3
  Top Layer w10: C37.1@700,953.62 U4.8@700,994.88
NetC34_1: C34.1 U4.3 | length 110.8
  Top Layer w10: C34.1@661.5,1200 700,1161.5 U4.3@700,1105.12
NetC41_1: C41.1 U3.37 | length 111.1
  Top Layer w10: C41.1@1070,1507.44 1077.56,1507.44 1090.69,1494.31 1097.73,1487.28 ; 1097.73,1487.27 1136.73,1448.27 U3.37@1156.61,1448.27
NetD1_1: D1.1 J1.2 Q8.1 Q8.2 Q8.3
NetD1_2: D1.2 Q1.2
NetD2_2: D2.2 R30.2 | length 71.1
  Top Layer w10: R30.2@1761,1306.38 1824.96,1306.38 D2.2@1830,1301.34
NetD3_1: D3.1 R31.1 | length 51.6
  Top Layer w10: D3.1@546,1048.53 546.38,1048.91 R31.1@546.38,1100
NetJ5_5: J5.5 R15.1 R16.2 R17.2 R18.2 | length 812.7
  Top Layer w10: R18.2@2246.38,930 2212.46,963.91 2212.46,975.87 2212.46,1126.09 R17.2@2246.38,1160 v1@2246.38,1193.62
  Top Layer w20: v1(2295,1380) 2293.62,1381.38 R16.2@2293.62,1410 2360,1410 J5.5@2400,1450 2400,1570 2383.62,1586.38 R15.1@2360,1586.38
  Bottom Layer w10: v1(2245,1200) 2295,1250 v1(2295,1380)
NetQ1_1: Q1.1 R2.1
NetQ1_3: Q1.3 Q8.4 R1.2 | length 516.9
  Bottom Layer w20: v1(1035,510) 960,510 940,490 940,210 985,165 v1(1055,165)
NetR20_1: R20.1 U3.44 | length 624.8
  Top Layer w10: v3(1107,1308) 1110,1308 1112.47,1310.47 U3.44@1156.61,1310.47 ; R20.1@1325,1641.38 1341.38,1641.38 v1(1365,1665)
  PVDD w10: v3(1107,1308) 1116,1308 1119,1305 1140,1326 1140,1418.89 1142,1420.89 1142,1423.04 1259.96,1541 1344,1541 1365,1562 v1(1365,1665)
NetR22_2: R22.2 U3.16 | length 1512.4
  Top Layer w10: v1(165,1060) R22.2@206.38,1060 ; v1(1441,1291) 1441.21,1290.79 U3.16@1483.39,1290.79
  PVDD w10: v1(165,1060) 295.7,1060 331.17,1095.46 513.46,1095.46 528,1110 528,1172.08 578.92,1223 1407.92,1223 1441,1256.08 v1(1441,1291)
NetR23_2: R23.2 U3.17 | length 1888.7
  Top Layer w10: v1(165,900) R23.2@206.38,900 ; U3.17@1483.39,1310.47 1518.53,1310.47 v1(1531,1298)
  PVDD w10: v1(165,900) 141,876 141,831 162,810 186.81,810 276.81,900 500,900 563.04,963.04 563.04,1159.04 593,1189 1422,1189 v1(1531,1298)
NetR25_2: R25.2 U3.18 | length 1700
  Top Layer w10: v1(165,855) R25.2@206.38,855 ; v1(1441,1330) 1441.16,1330.16 U3.18@1483.39,1330.16
  PVDD w10: v1(165,855) 310,1000 490,1000 545,1055 545,1165.04 585.96,1206 1414.96,1206 1467,1258.04 1467,1304 v1(1441,1330)
NFAULT: J3.6 R29.1 R30.1 U3.8 | length 2803.9
  Top Layer w10: U3.8@1349.53,1176.61 1349.53,1137.47 1380,1107 v1(1380,1085) ; R29.1@1710,1353.62 R30.1@1761,1353.62 1793.62,1353.62 1795,1355 v1(1810,1355)
  PVDD w10: v1(1380,1085) 1380,1089.92 1415.08,1125 1416.06,1125 1420.06,1129 1471.23,1129 1499.93,1100.31 1666.31,1100.31 1810,1244 v1(1810,1355)
  Bottom Layer w10: J3.6@350,1450 399,1401 399,1035 438.54,995.46 468.83,995.46 501,963.3 501,717 550,668 1100,668 1380,948 v1(1380,1085)
POSN_A: J4.14 R19.2 R26.2 | length 780
  Top Layer w10: J4.14@2050,1050 2100,1100 2100,1483 2119,1502 2190,1502 2225,1537 2256.62,1537 R19.2@2293.62,1500 R26.2@2293.62,1595
POSN_B: J4.16 R21.2 R27.2 | length 314
  Top Layer w10: R27.2@2246.38,980 R21.2@2246.38,1070
  Bottom Layer w10: J4.16@2050,950 2085,950 2135,1000 2225,1000 v1(2245,1020)
POSN_C: J4.5 R24.2 R28.2 | length 725.8
  Top Layer w10: J4.5@2150,1450 2195,1405 2195,1369.3 2195.46,1368.83 2195.46,1331.17 2195,1330.7 2195,1269.3 2195.46,1268.83 2195.46,854.54 2220,830 R24.2@2246.38,830 R28.2@2246.38,780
